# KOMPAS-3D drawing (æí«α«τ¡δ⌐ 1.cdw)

Referenced files in /: k6, h9, s6
Referenced files in E:\Борис\Школа\Детали машин\РГР№2\: 2.cdw
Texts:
  Трехступенчатый коническо- цилиндрический редуктор
  125 1 126 1 127 1 128 0 50 1|SPDS|125 1 126 1 127 1 128 0 50 1
  129 1 130 1 131 1 132 0 50 1|SPDS|129 1 130 1 131 1 132 0 50 1
  min
  max
  Уровень
  масла
  Технические характеристики:
  1. Частота вращения ведущего вала n   = 1455,0 об/мин.
  2. Мощность на ведущем валу N  = 5,78 КВт.
  3. Крутящий момент на тихоходном валу Т  = 3220 Нм.
  4. Общее передаточное число Uобщ = 91.
  5. Коеффициент полезного действия   = 0,845
  Symbol type A
  Технические требования:
  1. Коническая закрутая пара должна иметь боковой зазор в зацеплении 0,2 мм.
  2. Пятно касания конических зубьев:
  Регулировку осуществляют путем перемещения ведущего вала через добавление регулировочных
  прокладок.
  3. Роликоподшипники регулируют при помощи установочной гайки и прокладок.
  4. Редуктор залить машинным маслом марки И-70А ГОСТ 20799-75.
  5. Цилиндрическая зубчатая пара должна иметь боковой зазор в зацеплении 0,15 мм.
  6. Пятно контакта цилиндрических зубьев:
  7. Плоскость разьема редуктора покрыть щелочным лаком или жидким стеклом.
  8. Редуктор подвергнуть холодной обкатке в течении двух часов, при этом зубчатые пары
  должны работать с равномерным шумом.
  Трехступенчатый коническо-
  цилиндрический редуктор
  ДГТУ
  Кафедра ОКМ
  Андросов А.А.
Dimensions and other numbers on the sheet: 2; 29; 30; 31; 32; 40; 41; 42; 44; 45; 46; 50; 51; 160; 378,46; 0,06; 218,46; 249,67; 628,13; 1027; 35; 38; 72; 84; 60; 56; 90; 85; 100; 485; 230; 6 отв.; 24; 405; 465; 490; 1; 3; 4; 5; 6; 7; 8; 9; 10; 11; 12; 13; 14; 15; 16; 17; 18; 19; 20; 21; 22; 23; 25; 26; 27; 28; 33; 34; 36; 37; 39; 43; 47; 48; 49; 52; 53; 54; 215; 220; 870; 1:2,5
